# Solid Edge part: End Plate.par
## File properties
Author: CADCIM
Template: NORMENG.PAR
Last saved by: CADCIM
Revision: 2
Application: Solid Edge
Density: 0 lbm/in^3
Accuracy: 0.99
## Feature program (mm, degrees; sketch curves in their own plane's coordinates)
sketch for "unnamed Protrusion 1" plane through (0, 0, 0) normal (0, 0, 1) x-axis (1, 0, 0)
  line (-50.8, 50.8) -> (-50.8, -50.8)
  line (-50.8, -50.8) -> (50.8, -50.8)
  line (50.8, -50.8) -> (50.8, 50.8)
  line (50.8, 50.8) -> (-50.8, 50.8)
  dimension (linear) = 50.8
  dimension (linear) = 50.8
extrude "unnamed Protrusion 1" add finite 12.7 along +normal
sketch for "Hole_2" plane through (0, 0, 12.7) normal (0, 0, 1) x-axis (0, 1, 0)
  hole centre (-38.1, 38.1) bore radius 3.175
  dimension (linear) = 38.1
hole "Hole_2" diameter 6.35 through
pattern "unnamed Pattern 1" of "Hole_2"
pattern "unnamed Pattern 2"
sketch for "Hole_3" plane through (0, 0, 12.7) normal (0, 0, 1) x-axis (0, 1, 0)
  hole centre (0, 0) bore radius 12.7
hole "Hole_3" diameter 25.4 through
sketch for "Hole_4" plane through (0, 0, 12.7) normal (0, 0, 1) x-axis (0, 1, 0)
  hole centre (0, -20.6375) bore radius 2.3812
hole "Hole_4" diameter 4.7625 through
pattern "unnamed Pattern 3" of "Hole_4"
pattern "unnamed Pattern 4"
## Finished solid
Body 1: solid body, 15 faces, 30 edges, 8 vertices.
  Faces by surface: cylinder 9, plane 6
  Edges by curve: circle 18, line 12
Bounding box of the edges (mm): 101.600 x 101.600 x 12.700, from (-50.8, -50.8, 0) to (50.8, 50.8, 12.7).
Cylindrical faces by radius (mm): R2.3812 x4, R3.175 x4, R12.7 x1
Planar faces by outward normal: +x 1, +y 1, +z 1, -x 1, -y 1, -z 1
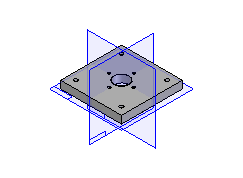
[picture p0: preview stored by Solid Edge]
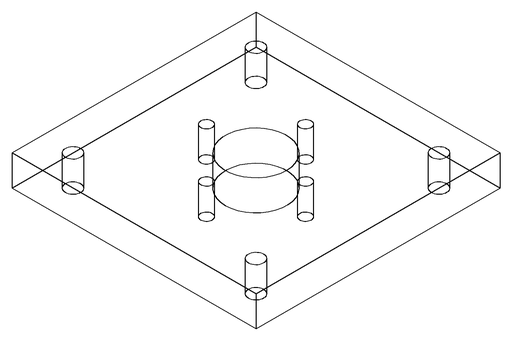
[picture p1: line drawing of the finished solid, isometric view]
